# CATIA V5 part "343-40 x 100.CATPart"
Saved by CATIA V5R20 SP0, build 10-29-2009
Part number: 343-40 x 100
Definition: NONE
Nomenclature: 343-40 x 100
Source: Unknown
Description: 343-40 x 100
Bounding box of the stored display mesh (mm): x 0 to 100, y -27.5 to 27.5, z -27.5 to 27.5
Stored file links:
  C:\Users\Utente\Desktop\IO LAVORO\3D X SITO CF\X SITO\343-348\343-40 x 100.CATPart
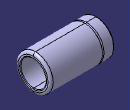
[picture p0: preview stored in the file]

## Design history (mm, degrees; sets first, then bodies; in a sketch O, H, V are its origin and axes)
Body1 "343-40 x 100" (main body)
  Solid1: solid without history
